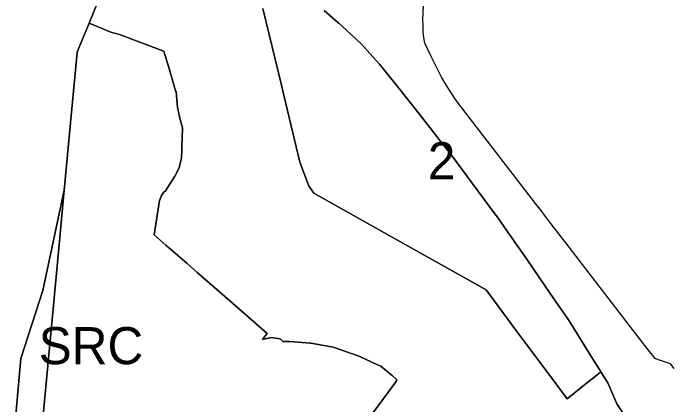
# Model space of a CAD drawing. Extents: x 598968 to 613553, y 4409678 to 4430833.
# Drawn here: x 607264.8 to 607478.1, y 4416782.2 to 4416909 of the extents above; entities that cross this region are included whole.
import ezdxf

# ---------------------------------------------------------------- set-up
doc = ezdxf.new("R2010")
doc.units = 0
for name, color, linetype in [('1', 7, 'Continuous'), ('Sòl Rústic Comú', 7, 'Continuous'), ('Sòl Rústic Protegit', 7, 'Continuous'), ('ZONA 2. CARRERS DE CASES. Cases de trast', 7, 'Continuous')]:
    doc.layers.add(name, color=color, linetype=linetype)

msp = doc.modelspace()

# ---------------------------------------------------------------- linework, layer by layer
at = {"layer": '1'}
for points in [[(607296.335, 4416922.9546), (607289.3373, 4416905.7947), (607296.4395, 4416902.8985), (607299.1695, 4416902.1086), (607313.2896, 4416896.8273), (607313.5793, 4416896.7189), (607315.2193, 4416891.409), (607316.8501, 4416885.7833), (607317.3966, 4416883.8979), (607317.5093, 4416883.5091), (607317.9693, 4416878.6092), (607318.7193, 4416875.0092), (607319.6293, 4416871.8593), (607319.5262, 4416868.437), (607319.447, 4416865.8019), (607319.408, 4416864.5069), (607319.3394, 4416862.2294), (607318.5094, 4416858.9094), (607317.1394, 4416856.2694), (607314.1395, 4416851.4694), (607313.5395, 4416851.0094), (607312.8495, 4416850.0194), (607312.1895, 4416848.3994), (607310.4596, 4416837.2295), (607314.2408, 4416833.9296), (607315.7655, 4416832.5991), (607319.4876, 4416829.3509), (607321.1031, 4416827.941), (607324.3828, 4416825.0788), (607329.9725, 4416820.2008), (607339.2024, 4416812.1458), (607347.0693, 4416805.2805), (607345.7945, 4416803.6199), (607345.5493, 4416803.3005), (607348.3093, 4416803.9906), (607351.0933, 4416803.5997), (607351.2292, 4416803.5806), (607351.9476, 4416802.9174), (607352.1392, 4416802.7407), (607354.0509, 4416802.6804), (607355.6292, 4416802.6307), (607360.9355, 4416802.1432), (607361.1791, 4416802.1208), (607364.8887, 4416801.4778), (607368.389, 4416800.871), (607371.879, 4416799.711), (607374.299, 4416798.8411), (607374.9643, 4416798.6081), (607377.0689, 4416797.8711), (607380.9816, 4416796.0441), (607382.5757, 4416795.2998), (607383.6602, 4416794.7934), (607383.8789, 4416794.6913), (607384.5589, 4416794.1513), (607386.4589, 4416792.5914), (607387.0836, 4416792.0389), (607387.6582, 4416791.5308), (607388.7938, 4416790.5264), (607389.0023, 4416790.3208), (607389.1122, 4416790.2124), (607389.0739, 4416790.1603), (607388.7118, 4416789.667), (607386.3243, 4416786.4145), (607372.5667, 4416767.6727)], [(607463.6508, 4416777.477), (607460.3682, 4416782.4727), (607460.3481, 4416782.5189), (607457.3681, 4416789.3526), (607455.1522, 4416792.9071), (607454.3944, 4416792.2155), (607449.3632, 4416788.1875), (607444.2482, 4416784.0925), (607440.7703, 4416788.7609), (607437.2924, 4416793.4293), (607427.6253, 4416806.4055), (607417.9584, 4416819.3816), (607390.0387, 4416835.0359), (607362.1189, 4416850.6903), (607360.6026, 4416852.855), (607360.5289, 4416852.9602), (607359.1358, 4416856.8126), (607357.6689, 4416860.7701), (607352.4354, 4416882.4801), (607351.6689, 4416885.6597), (607345.6689, 4416910.5493)], [(607478.9057, 4416793.9758), (607477.8122, 4416795.3361), (607477.6757, 4416795.5058), (607476.7957, 4416795.7958), (607474.4945, 4416796.5627), (607472.9998, 4416797.061), (607472.7459, 4416797.1456), (607469.7259, 4416800.9254), (607444.8859, 4416833.2993), (607444.6062, 4416833.6638), (607440.0762, 4416839.5236), (607437.9062, 4416842.3234), (607435.1162, 4416845.9332), (607435.0502, 4416846.019), (607421.3664, 4416863.7923), (607411.8166, 4416876.0817), (607408.0166, 4416881.0315), (607405.173, 4416885.6546), (607403.5267, 4416888.3311), (607400.2275, 4416895.0141), (607398.0868, 4416899.3506), (607397.8455, 4416901.1177), (607397.6267, 4416902.7206), (607397.5547, 4416905.391), (607397.5167, 4416906.8005), (607397.5194, 4416906.8744), (607397.6915, 4416911.5041)], [(607365.4789, 4416909.8876), (607369.8486, 4416906.1498), (607370.2717, 4416905.7562), (607372.6957, 4416903.5012), (607377.4694, 4416899.0603), (607378.6545, 4416897.7576), (607380.2511, 4416896.0028), (607383.4285, 4416892.5102), (607388.008, 4416886.8546), (607388.4756, 4416886.2771), (607389.6972, 4416884.7683), (607396.3071, 4416876.3919), (607402.0032, 4416869.1128), (607403.4373, 4416867.2803), (607406.3967, 4416863.461), (607420.8264, 4416844.0658), (607421.6553, 4416842.9174), (607421.8318, 4416842.6729), (607425.786, 4416836.992), (607431.3526, 4416828.9944), (607438.7409, 4416818.2858), (607442.2304, 4416813.2282), (607444.8631, 4416809.4122), (607452.8171, 4416796.6531), (607454.8913, 4416793.3256), (607455.1522, 4416792.9071), (607457.3681, 4416789.3526), (607460.3481, 4416782.5189), (607460.3682, 4416782.4727), (607463.6508, 4416777.477)], [(607372.5667, 4416767.6727), (607386.3243, 4416786.4145), (607388.7118, 4416789.667), (607389.0739, 4416790.1603), (607389.1122, 4416790.2124), (607389.0023, 4416790.3208), (607388.7938, 4416790.5264), (607387.6582, 4416791.5308), (607387.0836, 4416792.0389), (607386.4589, 4416792.5914), (607384.5589, 4416794.1513), (607383.8789, 4416794.6913), (607383.6602, 4416794.7934), (607382.5757, 4416795.2998), (607380.9816, 4416796.0441), (607377.0689, 4416797.8711), (607374.9643, 4416798.6081), (607374.299, 4416798.8411), (607371.879, 4416799.711), (607368.389, 4416800.871), (607364.8887, 4416801.4778), (607361.1791, 4416802.1208), (607360.9355, 4416802.1432), (607355.6292, 4416802.6307), (607354.0509, 4416802.6804), (607352.1392, 4416802.7407), (607351.9476, 4416802.9174), (607351.2292, 4416803.5806), (607351.0933, 4416803.5997), (607348.3093, 4416803.9906), (607345.5493, 4416803.3005), (607345.7945, 4416803.6199), (607347.0693, 4416805.2805), (607339.2024, 4416812.1458), (607329.9725, 4416820.2008), (607324.3828, 4416825.0788), (607321.1031, 4416827.941), (607319.4876, 4416829.3509), (607315.7655, 4416832.5991), (607314.2408, 4416833.9296), (607310.4596, 4416837.2295), (607312.1895, 4416848.3994), (607312.8495, 4416850.0194), (607313.5395, 4416851.0094), (607314.1395, 4416851.4694), (607317.1394, 4416856.2694), (607318.5094, 4416858.9094), (607319.3394, 4416862.2294), (607319.408, 4416864.5069), (607319.447, 4416865.8019), (607319.5262, 4416868.437), (607319.6293, 4416871.8593), (607318.7193, 4416875.0092), (607317.9693, 4416878.6092), (607317.5093, 4416883.5091), (607317.3966, 4416883.8979), (607316.8501, 4416885.7833), (607315.2193, 4416891.409), (607313.5793, 4416896.7189), (607313.2896, 4416896.8273), (607299.1695, 4416902.1086), (607296.4395, 4416902.8985), (607289.3373, 4416905.7947), (607285.6307, 4416896.7051), (607285.4682, 4416896.3065), (607282.7924, 4416867.822), (607282.7921, 4416867.8186), (607282.2436, 4416861.9802), (607282.2432, 4416861.9763), (607281.2748, 4416851.666), (607279.6162, 4416834.0092), (607279.6141, 4416833.9874), (607279.6134, 4416833.9796), (607274.3176, 4416777.6053)]]:
    msp.add_lwpolyline(points, dxfattribs=at)
at = {"layer": 'Sòl Rústic Comú'}
msp.add_lwpolyline([(607271.7539, 4416750.3129), (607272.8234, 4416761.6984), (607274.3176, 4416777.6053), (607279.6134, 4416833.9796), (607279.6141, 4416833.9874), (607279.6162, 4416834.0092), (607281.2748, 4416851.666), (607274.3169, 4416819.1968), (607267.2543, 4416797.1968), (607264.7541, 4416769.1968), (607265.5914, 4416739.0381), (607269.4696, 4416743.0294), (607272.4947, 4416745.5064), (607272.6695, 4416745.6495), (607271.9864, 4416745.8358), (607271.3496, 4416746.0094)], close=True, dxfattribs=at)
at = {"layer": 'Sòl Rústic Protegit'}
msp.add_lwpolyline([(607264.7541, 4416769.1968), (607267.2543, 4416797.1968), (607274.3169, 4416819.1968), (607281.2748, 4416851.666), (607282.2432, 4416861.9763), (607282.2436, 4416861.9802), (607282.7921, 4416867.8186), (607282.7924, 4416867.822), (607285.4682, 4416896.3065), (607285.6307, 4416896.7051), (607289.3373, 4416905.7947), (607296.335, 4416922.9546)], dxfattribs=at)
at = {"layer": 'ZONA 2. CARRERS DE CASES. Cases de trast'}
msp.add_lwpolyline([(607345.6689, 4416910.5493), (607351.6689, 4416885.6597), (607352.4354, 4416882.4801), (607357.6689, 4416860.7701), (607359.1358, 4416856.8126), (607360.5289, 4416852.9602), (607360.6026, 4416852.855), (607362.1189, 4416850.6903), (607390.0387, 4416835.0359), (607417.9584, 4416819.3816), (607427.6253, 4416806.4055), (607437.2924, 4416793.4293), (607440.7703, 4416788.7609), (607444.2482, 4416784.0925), (607449.3632, 4416788.1875), (607454.3944, 4416792.2155), (607455.1522, 4416792.9071), (607454.8913, 4416793.3256), (607452.8171, 4416796.6531), (607444.8631, 4416809.4122), (607442.2304, 4416813.2282), (607438.7409, 4416818.2858), (607431.3526, 4416828.9944), (607425.786, 4416836.992), (607421.8318, 4416842.6729), (607421.6553, 4416842.9174), (607420.8264, 4416844.0658), (607406.3967, 4416863.461), (607403.4373, 4416867.2803), (607402.0032, 4416869.1128), (607396.3071, 4416876.3919), (607389.6972, 4416884.7683), (607388.4756, 4416886.2771), (607388.008, 4416886.8546), (607383.4285, 4416892.5102), (607380.2511, 4416896.0028), (607378.6545, 4416897.7576), (607377.4694, 4416899.0603), (607372.6957, 4416903.5012), (607370.2717, 4416905.7562), (607369.8486, 4416906.1498), (607365.4789, 4416909.8876)], dxfattribs=at)

# ---------------------------------------------------------------- texts
at = {"layer": 'Sòl Rústic Comú'}
msp.add_text('SRC', height=12, dxfattribs=at).set_placement((607273.0144, 4416795.352))
at = {"layer": 'ZONA 2. CARRERS DE CASES. Cases de trast'}
msp.add_text('2', height=12, dxfattribs=at).set_placement((607399.084, 4416855.2489))

doc.saveas('drawing.dxf')
